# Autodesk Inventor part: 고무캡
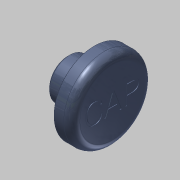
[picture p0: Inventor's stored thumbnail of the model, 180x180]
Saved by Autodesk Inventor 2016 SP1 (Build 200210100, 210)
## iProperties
Created: 2017-06
Part Number: 고무캡
Material: 고무
Document SubType Name: Modeling
Designer: mduedu
Density: 1 g/cm^3
Appearance: 고무 - 파란색 - 버전 1.1
Author: mduedu
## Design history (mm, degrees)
sketch "스케치1"
  geometry: L1 (0, 0)-(11, 0); L2 (11, 0)-(11, 10); L3 (11, 10)-(6.5, 10); L4 (0, 5)-(0, 0); L5 (0, 5)-(6, 5); L6 (6, 5)-(6, 9); L7 (6, 9)-(6.5, 9); L8 (6.5, 9)-(6.5, 10)
  constraints: 16 end point, 2 horizontal, 2 parallel, 2 perpendicular, 2 point on line, 1 vertical
  dimensions: "d0" = 20 diameter of L3 L1; "d2" = 10 diameter of L5 L1; "d6" = 5 distance between parallel lines of L2 L6; "d7" = 0.5 distance between parallel lines of L8 L6; "d8" = 18 diameter of L7 L1; "d9" = 6 distance between parallel lines of L6 L4
revolve "회전1" sketch "스케치1" stored, may be unused: angle "d10" = 90 deg
hole "구멍1" diameter "d22" = 7; stored, may be unused: countersink angle "d26" = 90 deg, drill point angle "d28" = 0 deg; dims "d23" = 6, "d24" = 4, "d25" = 2, "d27" = 6, "d32" = 10, "d33" = 10
chamfer "모따기1" distance "d13" = 0.5; stored, may be unused: second distance "d14" = 2, angle "d15" = 45 deg
fillet "모깎기3" dims "d29" = 1
fillet "모깎기1" dims "d16" = 0.1
fillet "모깎기2" dims "d17" = 2
sketch "스케치3"
  geometry: 2 further points
  constraints: 1 coincident, 1 other
feature "엠보싱1" sketch "스케치3" dims "d18" = 0.2, "d19" = 0
node "솔리드1"
